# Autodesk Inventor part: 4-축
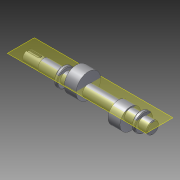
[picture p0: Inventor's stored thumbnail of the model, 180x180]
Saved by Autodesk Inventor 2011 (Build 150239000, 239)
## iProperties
Created: 2014-12
Part Number: 4-축
Document SubType Name: Modeling
Designer: user
Density: 1 g/cm^3
Author: user
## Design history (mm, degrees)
sketch "스케치2"
  geometry: L1 (-90, 0)-(90, 0); L2 (-90, 0)-(-90, 7.5); L3 (-90, 7.5)-(-66, 7.5); L4 (-66, 7.5)-(-66, 8.5); L5 (-66, 8.5)-(-39, 8.5); L6 (-39, 8.5)-(-39, 13); L7 (-39, 13)-(-34, 13); L8 (-34, 13)-(-34, 8.5); L9 (-34, 8.5)-(72, 8.5); L10 (72, 8.5)-(72, 13); L11 (72, 13)-(77, 13); L12 (77, 13)-(77, 8.5); L13 (77, 8.5)-(90, 8.5); L14 (90, 8.5)-(90, 0); 2 further points
  constraints: 28 end point, 11 parallel, 2 perpendicular, 1 coincident, 1 horizontal, 1 midpoint
  dimensions: "d0" = 180 distance of L1.start L1.end; "d1" = 24 distance of L2.end L3.end; "d2" = 27 distance of L4.end L5.end; "d3" = 5 distance of L6.end L7.end; "d4" = 13 distance of L12.end L13.end; "d5" = 5 distance of L10.end L11.end; "d6" = 15 diameter of L3 L1; "d7" = 17 diameter of L5 L1; "d8" = 26 diameter of L7 L1; "d9" = 17 diameter of L13 L1; "d10" = 26 diameter of L11 L1; "d11" = 17 diameter of L9 L1
revolve "회전1" sketch "스케치2" stored, may be unused: angle "d12" = 90 deg
chamfer "모따기1" distance "d13" = 1; stored, may be unused: second distance "d14" = 2, angle "d15" = 45 deg
node "작업 평면1"
sketch "스케치3"
  geometry: C1 r 15 at (-5, 0); 1 further point
  constraints: 1 centre point, 1 horizontal alignment
  dimensions: "d21" = 30 diameter of C1; "d22" = 5 distance of point (0, 0) C1.centre
extrude "돌출1" join sketch "스케치3" distance "d19" = 17; taper "d20" = 0 deg
node "작업 평면2"
sketch "스케치4"
  geometry: C1 r 17.5 at (-6, 0); 1 further point
  constraints: 1 centre point, 1 horizontal alignment
  dimensions: "d24" = 35 diameter of C1; "d25" = 6 distance of C1.centre point (0, 0)
extrude "돌출2" join sketch "스케치4" distance "d26" = 17; taper "d27" = 0 deg
node "작업 평면3"
sketch "스케치5"
  geometry: L1 (12, -2.5)-(-5.5, -2.5); L2 (-5.5, -2.5)-(-5.5, 2.5); L3 (-5.5, 2.5)-(12, 2.5); L4 (12, 2.5)-(12, -2.5); L5 (-12, 7.5)-(-12, -7.5) reference; L6 (11, -7.5)-(11, 7.5) reference; L7 (12, 6.5)-(12, -6.5) reference; A1 r 2.5 centre (-5.5, 0) between (-5.5, 2.5) and (-5.5, -2.5); 2 further points
  constraints: 8 end point, 2 midpoint, 2 parallel, 2 point on circle, 2 tangent, 1 centre point, 1 horizontal, 1 perpendicular
  dimensions: "d28" = 5 distance between parallel lines of L1 L3; "d29" = 20 dimension on A1 L4
extrude "돌출3" cut sketch "스케치5" distance "d30" = 3; taper "d31" = 0 deg
node "솔리드1"
node "투영된 루프1"
other parameters: "d16" = -49.5, "d23" = -70.5
